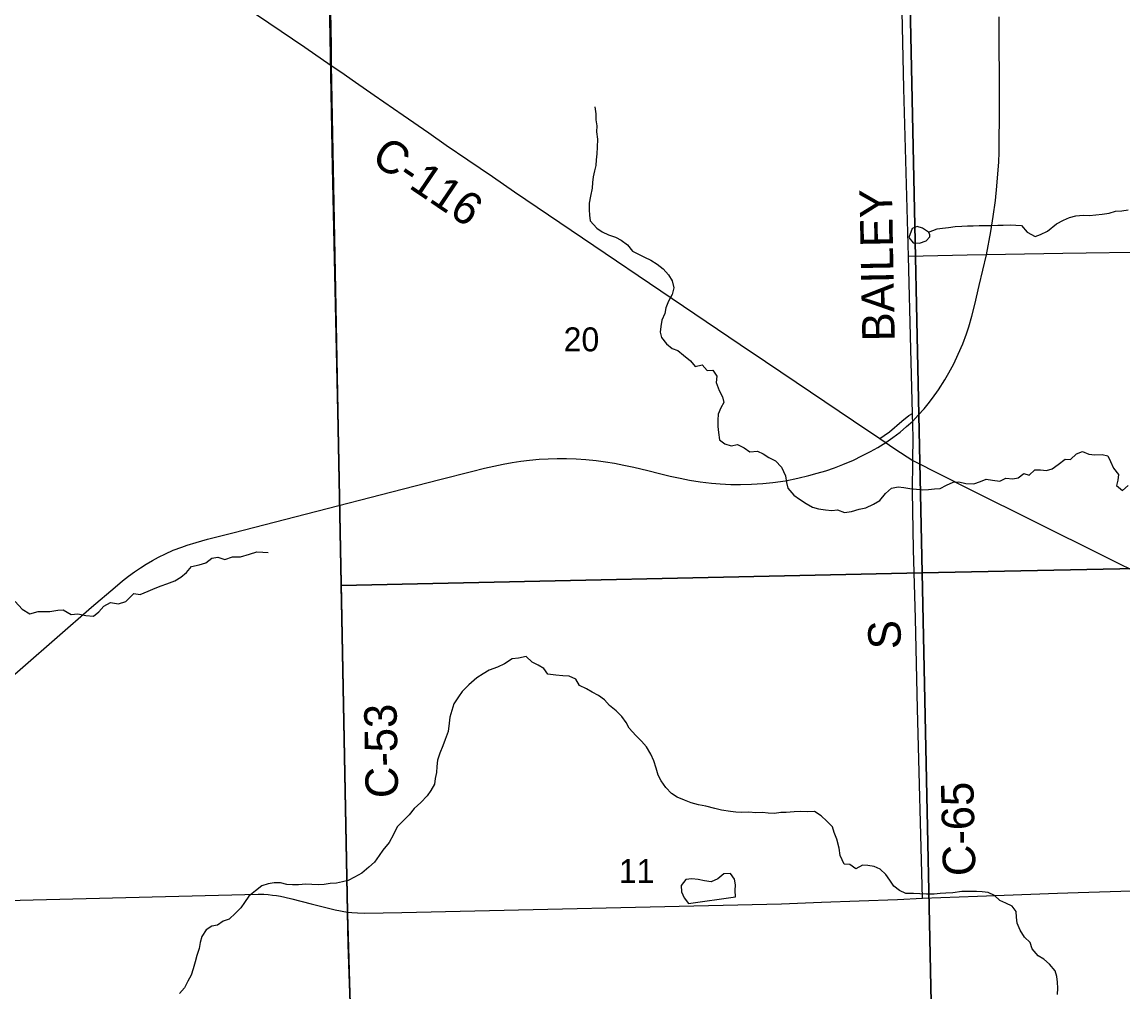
# Model space of a CAD drawing. Extents: x 0 to 34, y 0 to 22.
# Drawn here: x 6.498 to 8.421, y 16.025 to 17.72 of the extents above; entities that cross this region are included whole.
import ezdxf

# ---------------------------------------------------------------- set-up
doc = ezdxf.new("R2010")
doc.units = 0
for name, color, linetype in [('GM_X_Corporation', 7, 'Continuous'), ('GM_X_County_Road', 7, 'Continuous'), ('GM_X_County_Road_Text', 7, 'Continuous'), ('GM_X_Minor_Lake', 7, 'Continuous'), ('GM_X_Minor_River', 7, 'Continuous'), ('GM_X_Rail_Line', 7, 'Continuous'), ('GM_X_Section_Text', 7, 'Continuous'), ('GM_X_US_Route', 7, 'Continuous')]:
    doc.layers.add(name, color=color, linetype=linetype)

msp = doc.modelspace()

# ---------------------------------------------------------------- linework, layer by layer
at = {"layer": 'GM_X_Corporation'}
for points in [[(10.2438, 13.7323), (10.2438, 18.8341), (9.5705, 18.8263), (8.7622, 18.8099), (8.2239, 18.8028), (8.0146, 18.8), (7.0169, 18.7868), (7.0182, 18.7109), (7.0206, 18.595), (7.0233, 18.4737), (7.0259, 18.3381), (7.0286, 18.1986), (7.0307, 18.0432), (7.0341, 17.8886), (7.0383, 17.6784), (7.0382, 17.6446), (7.0667, 16.1653), (7.068, 16.109), (7.0714, 16.0063)], [(7.0714, 16.0063), (7.068, 16.109), (7.0667, 16.1653), (7.0382, 17.6446), (7.0383, 17.6784), (7.0341, 17.8886), (7.0307, 18.0432), (7.0286, 18.1986), (7.0259, 18.3381), (7.0233, 18.4737), (7.0206, 18.595), (7.0182, 18.7109), (7.0169, 18.7868), (5.8701, 18.7643)]]:
    msp.add_lwpolyline(points, dxfattribs=at)
for points in [[(8.0487, 17.7782), (9.0559, 17.7965), (9.0769, 16.778), (8.0702, 16.7576)], [(7.0352, 17.7584), (8.0487, 17.7782), (8.0702, 16.7576), (7.0559, 16.7358), (7.0543, 16.8256), (7.0404, 17.4662)], [(9.0769, 16.778), (9.1033, 15.7563), (8.0922, 15.7295), (8.0702, 16.7576)], [(8.0702, 16.7576), (8.0922, 15.7295), (7.0809, 15.7039), (7.0674, 16.1623), (7.0559, 16.7358)]]:
    msp.add_lwpolyline(points, close=True, dxfattribs=at)
at = {"layer": 'GM_X_County_Road'}
for points in [[(8.0538, 16.9541), (8.0548, 16.9942), (8.0537, 17.036), (8.0508, 17.1483), (8.0465, 17.3105), (8.0381, 17.6035), (8.0351, 17.7658), (8.0336, 17.8439), (8.0318, 17.9693), (8.0295, 18.0958), (8.0272, 18.236), (8.0254, 18.3738), (8.0236, 18.4658), (8.0212, 18.5961), (8.0183, 18.7814), (8.018, 18.7867), (8.0177, 18.7905), (8.0171, 18.7937), (8.0162, 18.7965), (8.0148, 18.7995), (8.0093, 18.8091)], [(7.0384, 17.644), (7.0385, 17.6779), (7.0343, 17.8881), (7.0309, 18.0426), (7.0288, 18.1981), (7.0261, 18.3375), (7.0235, 18.4731), (7.0208, 18.5944), (7.0184, 18.7103), (7.0171, 18.7863)], [(5.8782, 18.4947), (5.9358, 18.4461), (5.9936, 18.3971), (6.0268, 18.3689), (6.0904, 18.3159), (6.1681, 18.2524), (6.2428, 18.1922), (6.2813, 18.1619), (6.3094, 18.1413), (6.3342, 18.1241), (6.3678, 18.1015), (6.426, 18.0617), (6.4854, 18.0215), (6.563, 17.9686), (6.6015, 17.9424), (6.6318, 17.9214), (6.6751, 17.8917), (6.7318, 17.853), (6.7856, 17.8168), (6.8159, 17.7962), (6.865, 17.7629), (6.9294, 17.7186), (6.9925, 17.6757), (7.0384, 17.644)], [(7.1014, 14.6516), (7.0967, 15.1587), (7.0963, 15.1796), (7.0916, 15.3391), (7.0861, 15.5233), (7.0829, 15.6399), (7.0789, 15.7655), (7.0747, 15.8954), (7.0716, 16.0057), (7.0682, 16.1085), (7.0669, 16.1647), (7.0384, 17.644)], [(7.0384, 17.644), (7.055, 17.6327), (7.0807, 17.6147), (7.1134, 17.5919), (7.1642, 17.5569), (7.209, 17.5261), (7.2393, 17.505), (7.2771, 17.479), (7.3198, 17.4498), (7.3583, 17.4233), (7.7523, 17.1563), (7.7965, 17.1269), (7.8505, 17.0907), (7.9502, 17.0233), (7.9966, 16.9926), (8.0229, 16.9745), (8.0538, 16.9541)], [(8.4786, 17.318), (8.3163, 17.3156), (8.1488, 17.3129), (8.0465, 17.3105)], [(7.9966, 16.9926), (8.0041, 16.9977), (8.0132, 17.0041), (8.035, 17.0227), (8.0472, 17.0325), (8.0537, 17.036)], [(8.0709, 16.1891), (8.0623, 16.5201), (8.059, 16.6779), (8.0554, 16.7984), (8.0534, 16.9004), (8.0538, 16.9541)], [(8.0538, 16.9541), (8.1531, 16.9041), (8.3861, 16.788), (8.6182, 16.6729), (8.7178, 16.6239), (8.9166, 16.5259), (9.1215, 16.4246), (9.233, 16.3699), (9.36, 16.3074), (9.4823, 16.2467)]]:
    msp.add_lwpolyline(points, dxfattribs=at)
at = {"layer": 'GM_X_Minor_Lake'}
for points in [[(8.0817, 17.3528), (8.071, 17.3599), (8.0618, 17.3629), (8.0531, 17.3594), (8.0472, 17.3434), (8.0545, 17.3343), (8.0659, 17.3333), (8.0776, 17.3376), (8.0837, 17.3448), (8.084, 17.3486)], [(8.084, 17.3486), (8.0817, 17.3528)], [(7.7443, 16.1916), (7.7438, 16.2026), (7.7441, 16.2125), (7.7425, 16.2223), (7.7359, 16.2325), (7.7242, 16.2317), (7.7136, 16.2229), (7.7018, 16.2178), (7.69, 16.2196), (7.6794, 16.2222), (7.6683, 16.2233), (7.6577, 16.222), (7.6494, 16.2113), (7.6503, 16.2007), (7.6546, 16.1897), (7.6622, 16.1799)], [(7.7443, 16.1916), (7.7438, 16.2026), (7.7441, 16.2125), (7.7425, 16.2223), (7.7359, 16.2325), (7.7242, 16.2317), (7.7136, 16.2229), (7.7018, 16.2178), (7.69, 16.2196), (7.6794, 16.2222), (7.6683, 16.2233), (7.6577, 16.222), (7.6494, 16.2113), (7.6503, 16.2007), (7.6546, 16.1897), (7.6622, 16.1799), (7.6619, 16.181)], [(7.6622, 16.1799), (7.7443, 16.1916)]]:
    msp.add_lwpolyline(points, dxfattribs=at)
at = {"layer": 'GM_X_Minor_River'}
for points in [[(7.499, 17.572), (7.5006, 17.5595), (7.5007, 17.5489), (7.5023, 17.5386), (7.5016, 17.528), (7.5033, 17.515), (7.503, 17.5014), (7.502, 17.4896), (7.5013, 17.4793), (7.5006, 17.4694), (7.4981, 17.4599), (7.4959, 17.4496), (7.4948, 17.4393), (7.4938, 17.4295), (7.4912, 17.4154), (7.489, 17.4032), (7.4888, 17.3918), (7.4892, 17.3823), (7.4908, 17.3728), (7.502, 17.36), (7.5116, 17.3532), (7.5226, 17.3483), (7.5348, 17.3439), (7.5448, 17.3386), (7.5555, 17.3304), (7.5647, 17.3198), (7.575, 17.3146), (7.5857, 17.3093), (7.5964, 17.3037), (7.6075, 17.2966), (7.6179, 17.2887), (7.6271, 17.2781), (7.634, 17.2675), (7.6368, 17.2557), (7.6335, 17.2439), (7.6271, 17.2321), (7.6226, 17.2207), (7.6208, 17.2108), (7.616, 17.1989), (7.6138, 17.1879), (7.6131, 17.178), (7.6151, 17.1685), (7.624, 17.158), (7.6339, 17.1497), (7.6435, 17.146), (7.6538, 17.1381), (7.6657, 17.1283), (7.6741, 17.1181), (7.6859, 17.1212), (7.6947, 17.1114), (7.705, 17.1115), (7.7119, 17.1013), (7.7105, 17.0902), (7.716, 17.0762), (7.7218, 17.0652), (7.7238, 17.0554), (7.7185, 17.0458), (7.714, 17.0351), (7.7138, 17.0241), (7.7135, 17.0135), (7.7147, 17.0028), (7.7163, 16.9903), (7.7259, 16.9828), (7.737, 16.9795), (7.7476, 16.9818), (7.7594, 16.9758), (7.7694, 16.9691), (7.7827, 16.9703), (7.7926, 16.9658), (7.8026, 16.9591), (7.8144, 16.9531), (7.8248, 16.9421), (7.8318, 16.9274), (7.8334, 16.9152), (7.8358, 16.9057), (7.8461, 16.8933), (7.8561, 16.8861), (7.8676, 16.8786), (7.8786, 16.8726), (7.8893, 16.8693), (7.9015, 16.8675), (7.9126, 16.8664), (7.9228, 16.868), (7.935, 16.8632), (7.9472, 16.8648), (7.9601, 16.8687), (7.9722, 16.8711), (7.9855, 16.8777), (7.9965, 16.8838), (8.0066, 16.8961), (8.0168, 16.9057), (8.0282, 16.908), (8.0381, 16.9066), (8.0491, 16.9052), (8.0606, 16.9037), (8.0716, 16.9027), (8.0815, 16.9031), (8.0917, 16.9047), (8.102, 16.9048), (8.113, 16.9106), (8.1247, 16.916)], [(8.0817, 17.3528), (8.0965, 17.3586), (8.106, 17.3595), (8.1162, 17.3611), (8.128, 17.3627), (8.1394, 17.3631), (8.1497, 17.3636), (8.1596, 17.3637), (8.1702, 17.3645), (8.1915, 17.3647), (8.2025, 17.3652), (8.212, 17.3649), (8.2238, 17.3657), (8.2337, 17.365), (8.2436, 17.3647), (8.254, 17.353), (8.2677, 17.3455), (8.2772, 17.349), (8.2893, 17.3545), (8.3048, 17.3671), (8.3173, 17.3737), (8.3279, 17.3787), (8.3386, 17.3811), (8.3515, 17.3823), (8.3625, 17.382), (8.3739, 17.3833), (8.3846, 17.3841), (8.3971, 17.3861), (8.4081, 17.3892), (8.4191, 17.3901), (8.4301, 17.3917)], [(8.1247, 16.916), (8.1342, 16.9169), (8.1468, 16.9135), (8.1609, 16.9133), (8.1723, 16.9175), (8.1821, 16.9214), (8.1932, 16.9196), (8.2061, 16.9178), (8.2167, 16.9228), (8.2285, 16.9218), (8.238, 16.9234), (8.2478, 16.9311), (8.2574, 16.9281), (8.2672, 16.9377), (8.2771, 16.9378), (8.2873, 16.9363), (8.2972, 16.9391), (8.3078, 16.9467), (8.3199, 16.9563), (8.3294, 16.9557), (8.3399, 16.9656), (8.3502, 16.9695), (8.3616, 16.9647), (8.3719, 16.964), (8.3848, 16.9645), (8.3944, 16.9619), (8.3994, 16.952), (8.4048, 16.9407), (8.4133, 16.9293), (8.4119, 16.9198), (8.4097, 16.9103), (8.42, 16.9013), (8.4302, 16.9105)], [(6.8191, 16.7753), (6.83, 16.7831), (6.8406, 16.7853), (6.8524, 16.781), (6.866, 16.7859), (6.8801, 16.7854), (6.8956, 16.7903), (6.9084, 16.7945), (6.9187, 16.7939), (6.9282, 16.7934)], [(6.4863, 16.7074), (6.4988, 16.6944), (6.5123, 16.686), (6.5263, 16.6901), (6.5373, 16.6904), (6.5472, 16.6899), (6.5609, 16.6925), (6.5704, 16.6931), (6.5842, 16.685), (6.5956, 16.686), (6.6098, 16.6833), (6.6231, 16.6821), (6.6328, 16.6896), (6.641, 16.6993), (6.6526, 16.7056), (6.6667, 16.7037), (6.6796, 16.7074), (6.6937, 16.7214), (6.7048, 16.7201), (6.7187, 16.7254), (6.7307, 16.731), (6.7413, 16.7351), (6.7511, 16.7383), (6.7654, 16.7436), (6.7759, 16.7503), (6.7856, 16.7581), (6.7945, 16.769), (6.8078, 16.7716), (6.8191, 16.7753)], [(7.5803, 16.4635), (7.5703, 16.4733), (7.5588, 16.4862), (7.5537, 16.496), (7.5456, 16.5066), (7.5357, 16.5164), (7.5246, 16.5258), (7.5157, 16.536), (7.5054, 16.5435), (7.4943, 16.5495), (7.484, 16.5551), (7.4721, 16.5607), (7.4656, 16.5717), (7.4541, 16.5769), (7.4427, 16.578), (7.4305, 16.5787), (7.4168, 16.5808), (7.4095, 16.5907), (7.3996, 16.5963), (7.3893, 16.6019), (7.3789, 16.6117), (7.3656, 16.6089), (7.3546, 16.6073), (7.341, 16.5989), (7.3285, 16.5927), (7.3141, 16.5876), (7.3035, 16.5814), (7.2925, 16.5741), (7.2789, 16.5622), (7.2669, 16.5504), (7.2605, 16.5408), (7.2526, 16.5286), (7.2489, 16.5172), (7.2456, 16.5057), (7.2441, 16.4951), (7.2424, 16.4806), (7.2375, 16.4665), (7.2335, 16.4555), (7.2279, 16.4425), (7.2242, 16.4307), (7.2227, 16.4196), (7.2221, 16.409), (7.2199, 16.3983), (7.2185, 16.3884), (7.2121, 16.3777), (7.2057, 16.3682), (7.1948, 16.3567), (7.1835, 16.346), (7.1744, 16.3349), (7.1639, 16.3245), (7.1537, 16.3142), (7.1473, 16.3008), (7.1395, 16.2867), (7.1286, 16.2733), (7.1222, 16.2638), (7.1139, 16.2523), (7.1041, 16.2435), (7.092, 16.2331), (7.0788, 16.2258), (7.0678, 16.2204), (7.0583, 16.218), (7.0473, 16.2153), (7.0367, 16.2148), (7.026, 16.2132), (7.0161, 16.2127), (7.0043, 16.213), (6.9941, 16.2137), (6.9811, 16.2125), (6.9709, 16.2124), (6.9606, 16.2134), (6.9499, 16.216), (6.9385, 16.2159), (6.9283, 16.2143), (6.9173, 16.2112), (6.9063, 16.2023), (6.8946, 16.1928), (6.8871, 16.182), (6.8807, 16.1725), (6.8709, 16.1633), (6.8603, 16.1529), (6.8497, 16.1491), (6.8399, 16.1425), (6.83, 16.1402), (6.8198, 16.134), (6.8123, 16.1222), (6.8094, 16.1119), (6.8076, 16.1012), (6.8035, 16.0894), (6.8009, 16.078), (6.7972, 16.0658), (6.7939, 16.0551), (6.7879, 16.0444), (6.7819, 16.033), (6.7733, 16.0226)], [(8.3068, 16.0212), (8.3075, 16.0322), (8.307, 16.0428), (8.3054, 16.0523), (8.3026, 16.0626), (8.293, 16.0739), (8.2831, 16.0826), (8.2727, 16.0886), (8.2627, 16.1007), (8.2588, 16.112), (8.2489, 16.1214), (8.2415, 16.1332), (8.2365, 16.1457), (8.2352, 16.1559), (8.2344, 16.1658), (8.2278, 16.1756), (8.2164, 16.1809), (8.2061, 16.1853), (8.1965, 16.194), (8.1854, 16.1992), (8.1751, 16.2003), (8.1652, 16.201), (8.1546, 16.2013), (8.1394, 16.2008), (8.1238, 16.1988), (8.1116, 16.1983), (8.1021, 16.1974), (8.0915, 16.1962), (8.0782, 16.1961), (8.0664, 16.1972), (8.0554, 16.1975), (8.042, 16.1973), (8.0306, 16.203), (8.021, 16.2105), (8.0137, 16.2207), (8.0068, 16.2305), (7.9972, 16.2399), (7.9865, 16.2448), (7.9754, 16.2466), (7.9659, 16.2469), (7.9546, 16.2404), (7.9442, 16.2483), (7.9343, 16.2489), (7.927, 16.2641), (7.9254, 16.2766), (7.9214, 16.2922), (7.9167, 16.3043), (7.9136, 16.3138), (7.904, 16.324), (7.894, 16.3334), (7.8822, 16.3405), (7.87, 16.3404), (7.8582, 16.3407), (7.8468, 16.3402), (7.8331, 16.339), (7.8236, 16.3389), (7.8126, 16.3373), (7.8016, 16.338), (7.7913, 16.339), (7.7799, 16.3386), (7.7677, 16.3396), (7.7548, 16.3391), (7.7449, 16.3394), (7.7354, 16.3409), (7.7201, 16.343), (7.7083, 16.346), (7.6927, 16.35), (7.6797, 16.3526), (7.6672, 16.3559), (7.6553, 16.3604), (7.6424, 16.3656), (7.6328, 16.372), (7.6228, 16.3825), (7.6143, 16.3946), (7.6093, 16.4045), (7.6058, 16.4166), (7.6019, 16.4295), (7.5968, 16.4409), (7.5887, 16.4537), (7.5803, 16.4635)]]:
    msp.add_lwpolyline(points, dxfattribs=at)
at = {"layer": 'GM_X_Rail_Line'}
msp.add_lwpolyline([(6.4394, 16.5404), (6.6199, 16.6975), (6.6608, 16.7325), (6.6739, 16.7436), (6.6845, 16.7517), (6.6946, 16.7594), (6.7051, 16.7666), (6.7153, 16.773), (6.726, 16.779), (6.7366, 16.7849), (6.749, 16.791), (6.7626, 16.7974), (6.7775, 16.8028), (6.787, 16.8062), (6.8024, 16.8109), (6.8221, 16.8166), (6.8663, 16.8277), (7.0134, 16.8657), (7.1441, 16.8993), (7.2282, 16.9208), (7.2836, 16.9347), (7.3062, 16.9407), (7.3221, 16.9443), (7.3385, 16.9475), (7.3546, 16.9505), (7.3697, 16.9527), (7.3845, 16.9545), (7.4014, 16.956), (7.4172, 16.9569), (7.4331, 16.9574), (7.449, 16.9573), (7.4661, 16.9569), (7.4831, 16.9558), (7.5013, 16.9539), (7.5172, 16.9518), (7.5331, 16.9491), (7.5496, 16.946), (7.5671, 16.9422), (7.5915, 16.9364), (7.6117, 16.9313), (7.6305, 16.9268), (7.6479, 16.9228), (7.6642, 16.9197), (7.6824, 16.9167), (7.7025, 16.9145), (7.7175, 16.913), (7.7363, 16.9121), (7.753, 16.912), (7.7722, 16.9123), (7.7922, 16.9138), (7.8097, 16.9155), (7.832, 16.9186), (7.8533, 16.9229), (7.8726, 16.9275), (7.8873, 16.9316), (7.9023, 16.9361), (7.9172, 16.9412), (7.9317, 16.9468), (7.9503, 16.9547), (7.9652, 16.9618), (7.98, 16.9695), (7.9929, 16.9766), (8.0069, 16.9851), (8.019, 16.9941), (8.0318, 17.0037), (8.0431, 17.0133), (8.0538, 17.0229), (8.0634, 17.0329), (8.0736, 17.0441), (8.081, 17.053), (8.0884, 17.0626), (8.0988, 17.0772), (8.1099, 17.0946), (8.1172, 17.1069), (8.1255, 17.1225), (8.1331, 17.1395), (8.1413, 17.1576), (8.1478, 17.1754), (8.1519, 17.1877), (8.1572, 17.206), (8.1623, 17.2267), (8.1702, 17.2599), (8.1825, 17.3134), (8.1904, 17.3537), (8.1945, 17.3801), (8.1982, 17.408), (8.2008, 17.4332), (8.2026, 17.4548), (8.2041, 17.4751), (8.2047, 17.4923), (8.2054, 17.5732), (8.205, 17.7287)], dxfattribs=at)
at = {"layer": 'GM_X_US_Route'}
for points in [[(7.0669, 16.1647), (7.0746, 16.1643), (7.0844, 16.1637), (7.0963, 16.1634), (7.1618, 16.1645), (7.825, 16.1797), (7.8946, 16.1823), (7.9604, 16.1847), (8.0272, 16.1873), (8.0709, 16.1891), (8.167, 16.1931), (8.3066, 16.1984), (8.3428, 16.1995), (8.4171, 16.2016), (8.4871, 16.2031), (8.5373, 16.2045), (8.674, 16.2072), (8.8546, 16.2105), (9.0191, 16.2135), (9.188, 16.2172), (9.3008, 16.2197)], [(5.2776, 16.1613), (5.4637, 16.1632), (5.6965, 16.1672), (6.015, 16.1736), (6.24, 16.1796), (6.9107, 16.1964), (6.9209, 16.1962), (6.9282, 16.1958), (6.9358, 16.1949), (6.9426, 16.194), (6.9496, 16.1926), (6.9572, 16.191), (6.9696, 16.1881), (7.0031, 16.1797), (7.0451, 16.169), (7.0669, 16.1647)]]:
    msp.add_lwpolyline(points, dxfattribs=at)

# ---------------------------------------------------------------- texts
at = {"layer": 'GM_X_County_Road_Text'}
for s, height, rotation, p in [('C-116', 0.05682, 325.9294, (7.1056, 17.4761)), ('BAILEY', 0.05682, 91.1161, (8.0227, 17.1625)), ('S', 0.0568, 91.2448, (8.0335, 16.6249)), ('C-53', 0.05682, 91.0286, (7.1554, 16.3646)), ('C-65', 0.05682, 91.3713, (8.1637, 16.2285))]:
    msp.add_text(s, height=height, rotation=rotation, dxfattribs=at).set_placement(p)
at = {"layer": 'GM_X_Section_Text'}
for s, p in [('20', (7.4442, 17.1446)), ('11', (7.5405, 16.2158))]:
    msp.add_text(s, height=0.04186, rotation=0, dxfattribs=at).set_placement(p)

doc.saveas('drawing.dxf')
